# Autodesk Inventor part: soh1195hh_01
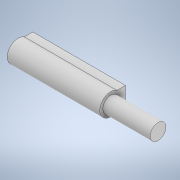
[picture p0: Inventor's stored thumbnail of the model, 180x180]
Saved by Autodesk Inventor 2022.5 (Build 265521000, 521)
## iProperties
Created: 2023-06
Part Number: soh1195hh_01
Material: Generic
Document SubType Name: Modeling
Designer: ImaoCorp
Density: 1 g/cm^3
Appearance: Default
Author: ImaoCorp
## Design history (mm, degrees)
feature "soh1195hh_01"
node "ソリッド1"
